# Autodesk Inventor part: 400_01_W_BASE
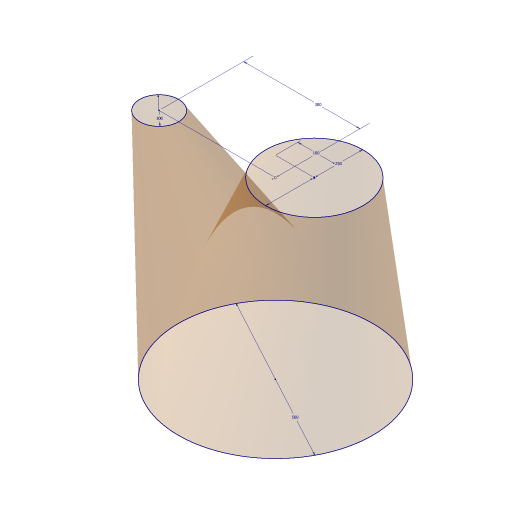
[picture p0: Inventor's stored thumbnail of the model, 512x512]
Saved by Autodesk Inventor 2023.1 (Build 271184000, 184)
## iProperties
Created: 2011-01
Part Number: 400_01_W_BASE
Document SubType Name: Modeling
Designer: F.Stasiak
Density: 1 g/cm^3
Material: Ogólny
Appearance: Domyślna
Catalog Web Link: www.expertbooks.eu
Company: Fabian Stasiak CAD Consulting
Category: Autodesk® Inventor® Tutorial Series
Author: F.Stasiak
Subject: Sheet Metal Design. Basic and Advanced techniques
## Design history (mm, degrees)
sketch "Szkic1"
  geometry: C1 r 250 at (0, 0); 1 further point
  constraints: 1 centre point, 1 coincident
  dimensions: "d0" = 500 diameter of C1
node "Płaszczyzna konstrukcyjna1"
sketch "Szkic2"
  geometry: C1 r 50 at (-300, 0); 1 further point
  constraints: 1 centre point
  dimensions: "d2" = 100 diameter of C1; "d3" = 300 distance of point (0, 0) C1.centre; "d4" = 0 vertical distance of point (0, 0) C1.centre
node "Płaszczyzna konstrukcyjna2"
sketch "Szkic3"
  geometry: C1 r 125 at (100, 0); 1 further point
  constraints: 1 centre point
  dimensions: "d6" = 250 diameter of C1; "d7" = 100 distance of point (0, 0) C1.centre; "d8" = 0 vertical distance of point (0, 0) C1.centre
feature "PowWyciągnięciaZłożonego1" dims "d9" = 0, "d10" = 90 deg, "d11" = 0, "d12" = 90 deg
feature "PowWyciągnięciaZłożonego2" dims "d13" = 0, "d14" = 90 deg, "d15" = 0, "d16" = 90 deg
  node "Krawędzie1"
feature "Utnij1"
feature "Utnij2"
node "Bryła1"
body "Srf1"
body "Srf2"
